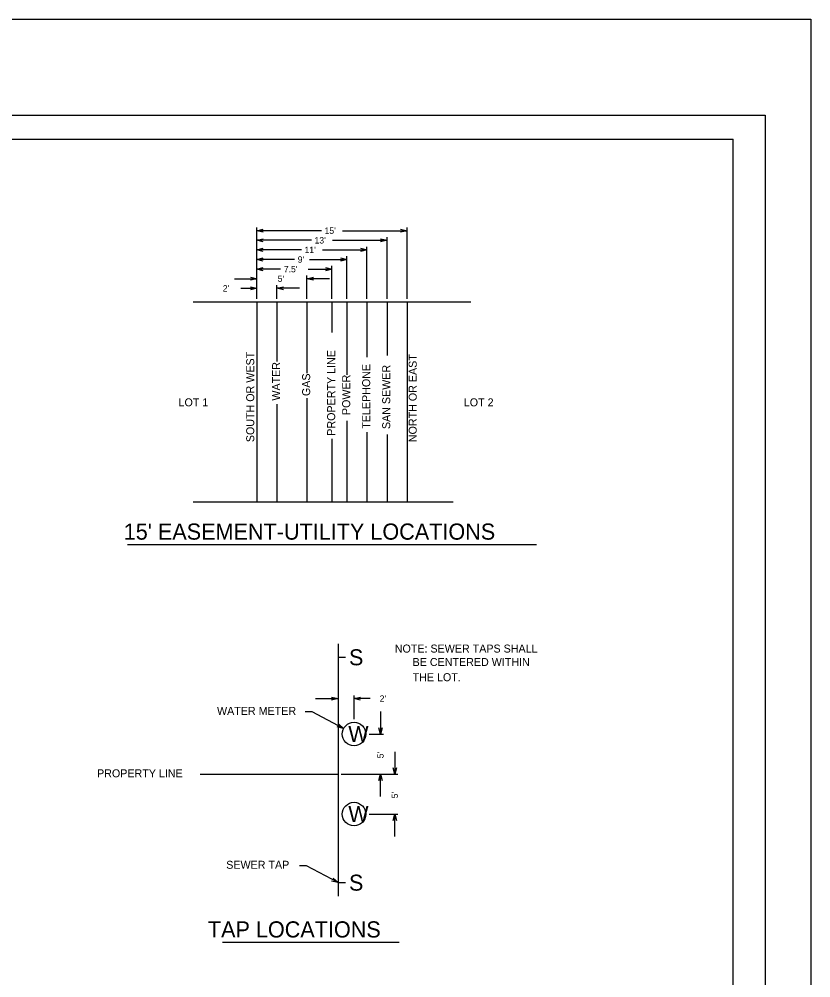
# Model space of a CAD drawing. Extents: x 524397 to 525117, y 3701341 to 3701821.
# Drawn here: x 524919 to 525116.8, y 3701581.4 to 3701821 of the extents above; entities that cross this region are included whole.
import ezdxf

# ---------------------------------------------------------------- set-up
doc = ezdxf.new("R2010")
doc.units = 0
for name, color, linetype in [('Level 1', 7, 'Continuous'), ('Level 11', 7, 'Continuous'), ('Level 9', 7, 'Continuous'), ('Pam batch print border', 7, 'Continuous')]:
    doc.layers.add(name, color=color, linetype=linetype)

msp = doc.modelspace()

# ---------------------------------------------------------------- linework, layer by layer
at = {"layer": 'Level 1'}
for p, q in [((524442.4, 3701790.98), (525097.4, 3701790.98)), ((525097.4, 3701370.98), (525097.4, 3701790.98)), ((524962.45, 3701750.32), (525031.86, 3701750.32)), ((524997.15, 3701750.32), (524997.15, 3701742.64)), ((524997.15, 3701716.03), (524997.15, 3701700.32)), ((524962.45, 3701700.32), (525027.45, 3701700.32)), ((524946.08, 3701689.72), (525048.22, 3701689.72)), ((524998.66, 3701664.86), (524998.66, 3701601.79)), ((524964.22, 3701632.3), (524998.66, 3701632.3)), ((524969.78, 3701590.3), (525013.95, 3701590.3))]:
    msp.add_line(p, q, dxfattribs=at)
at = {"layer": 'Level 11'}
for p, q in [((524978.4, 3701751.12), (524978.4, 3701768.92)), ((524978.4, 3701768.12), (524980, 3701768.52)), ((524994.5, 3701768.12), (524978.4, 3701768.12)), ((524980, 3701767.72), (524978.4, 3701768.12)), ((524999.81, 3701768.12), (525015.9, 3701768.12)), ((525014.3, 3701768.52), (525015.9, 3701768.12)), ((525015.9, 3701768.12), (525014.3, 3701767.72)), ((525015.9, 3701751.12), (525015.9, 3701768.92)), ((524978.4, 3701751.12), (524978.4, 3701766.52)), ((524978.4, 3701765.72), (524980, 3701766.12)), ((524992, 3701765.72), (524978.4, 3701765.72)), ((524980, 3701765.31), (524978.4, 3701765.72)), ((524997.31, 3701765.72), (525010.9, 3701765.72)), ((525009.3, 3701766.12), (525010.9, 3701765.72)), ((525010.9, 3701765.72), (525009.3, 3701765.31)), ((525010.9, 3701751.12), (525010.9, 3701766.52)), ((524978.4, 3701751.12), (524978.4, 3701764.11)), ((524978.4, 3701763.31), (524980, 3701763.71)), ((524989.5, 3701763.31), (524978.4, 3701763.31)), ((524980, 3701762.91), (524978.4, 3701763.31)), ((524994.81, 3701763.31), (525005.9, 3701763.31)), ((525004.3, 3701763.71), (525005.9, 3701763.31)), ((525005.9, 3701763.31), (525004.3, 3701762.91)), ((525005.9, 3701751.12), (525005.9, 3701764.11)), ((524978.4, 3701751.12), (524978.4, 3701761.71)), ((524978.4, 3701760.91), (524980, 3701761.31)), ((524987.79, 3701760.91), (524978.4, 3701760.91)), ((524980, 3701760.51), (524978.4, 3701760.91)), ((524991.51, 3701760.91), (525000.9, 3701760.91)), ((524999.3, 3701761.31), (525000.9, 3701760.91)), ((525000.9, 3701760.91), (524999.3, 3701760.51)), ((525000.9, 3701751.12), (525000.9, 3701761.71)), ((524978.4, 3701751.12), (524978.4, 3701759.31)), ((524978.4, 3701758.51), (524980, 3701758.91)), ((524984.33, 3701758.51), (524978.4, 3701758.51)), ((524980, 3701758.11), (524978.4, 3701758.51)), ((524991.22, 3701758.51), (524997.15, 3701758.51)), ((524995.55, 3701758.91), (524997.15, 3701758.51)), ((524997.15, 3701758.51), (524995.55, 3701758.11)), ((524997.15, 3701751.12), (524997.15, 3701759.31)), ((524972.8, 3701756.11), (524978.4, 3701756.11)), ((524976.8, 3701756.51), (524978.4, 3701756.11)), ((524978.4, 3701756.11), (524976.8, 3701755.71)), ((524978.4, 3701751.12), (524978.4, 3701756.91)), ((524990.9, 3701751.12), (524990.9, 3701756.91)), ((524990.9, 3701756.11), (524992.5, 3701756.51)), ((524996.51, 3701756.11), (524990.9, 3701756.11)), ((524992.5, 3701755.71), (524990.9, 3701756.11)), ((524974.4, 3701753.71), (524978.4, 3701753.71)), ((524976.8, 3701754.11), (524978.4, 3701753.71)), ((524978.4, 3701753.71), (524976.8, 3701753.31)), ((524978.4, 3701751.12), (524978.4, 3701754.51)), ((524983.4, 3701751.12), (524983.4, 3701754.51)), ((524983.4, 3701753.71), (524985, 3701754.11)), ((524989.01, 3701753.71), (524983.4, 3701753.71)), ((524985, 3701753.31), (524983.4, 3701753.71)), ((524978.4, 3701750.32), (524978.4, 3701700.32)), ((524983.4, 3701750.32), (524983.4, 3701735.42)), ((524990.9, 3701750.32), (524990.9, 3701732.53)), ((525000.9, 3701750.32), (525000.9, 3701732.07)), ((525005.9, 3701750.32), (525005.9, 3701736.52)), ((525010.9, 3701750.32), (525010.9, 3701736.93)), ((525015.9, 3701750.32), (525015.9, 3701700.32)), ((524983.4, 3701724.78), (524983.4, 3701700.32)), ((524990.9, 3701726.24), (524990.9, 3701700.32)), ((525000.9, 3701720.59), (525000.9, 3701700.32)), ((525005.9, 3701717.74), (525005.9, 3701700.32)), ((524997.15, 3701716.1), (524997.15, 3701700.32)), ((525010.9, 3701717.17), (525010.9, 3701700.32)), ((524998.66, 3701664.06), (524998.66, 3701650.36)), ((524998.66, 3701661.49), (525000.56, 3701661.49)), ((524993.06, 3701651.16), (524998.66, 3701651.16)), ((525002.66, 3701646.04), (525002.66, 3701651.97)), ((525006.66, 3701651.16), (525002.66, 3701651.16)), ((525009.25, 3701647.9), (525009.25, 3701642.3)), ((525006.41, 3701642.3), (525010.05, 3701642.3)), ((525012.84, 3701637.9), (525012.84, 3701632.3)), ((524999.46, 3701632.3), (525010.05, 3701632.3)), ((524999.46, 3701632.3), (525013.64, 3701632.3)), ((525009.25, 3701626.69), (525009.25, 3701632.3)), ((525006.41, 3701622.3), (525013.64, 3701622.3)), ((525012.84, 3701616.69), (525012.84, 3701622.3)), ((524998.66, 3701605.16), (525000.56, 3701605.16))]:
    msp.add_line(p, q, dxfattribs=at)
for points in [[(524997.06, 3701651.56), (524998.66, 3701651.16), (524997.06, 3701650.76)], [(525004.26, 3701650.76), (525002.66, 3701651.16), (525004.26, 3701651.56)], [(525000.07, 3701643.68), (524992.22, 3701647.87), (524990.42, 3701647.87)], [(524998.84, 3701644.79), (525000.07, 3701643.68), (524998.46, 3701644.08)], [(525009.65, 3701643.9), (525009.25, 3701642.3), (525008.85, 3701643.9)], [(525013.24, 3701633.9), (525012.84, 3701632.3), (525012.44, 3701633.9)], [(525008.85, 3701630.69), (525009.25, 3701632.3), (525009.65, 3701630.69)], [(525012.44, 3701620.69), (525012.84, 3701622.3), (525013.24, 3701620.69)], [(524998.66, 3701605.16), (524990.82, 3701609.36), (524989.02, 3701609.36)], [(524997.44, 3701606.27), (524998.66, 3701605.16), (524997.06, 3701605.57)]]:
    msp.add_lwpolyline(points, dxfattribs=at)
for centre in [(525002.66, 3701642.3), (525002.66, 3701622.3)]:
    msp.add_circle(centre, 2.94, dxfattribs=at)
at = {"layer": 'Level 9'}
msp.add_lwpolyline([(524396.79, 3701820.98), (525116.79, 3701820.98), (525116.79, 3701340.98), (524396.79, 3701340.98)], close=True, dxfattribs=at)
at = {"layer": 'Pam batch print border'}
msp.add_lwpolyline([(524433.4, 3701796.98), (525105.4, 3701796.98), (525105.4, 3701364.98), (524433.4, 3701364.98)], close=True, dxfattribs=at)
msp.add_lwpolyline([(524433.4, 3701796.98), (525105.4, 3701796.98), (525105.4, 3701364.98), (524433.4, 3701364.98)], close=True, dxfattribs=at)

# ---------------------------------------------------------------- texts
at = {"layer": 'Level 1'}
for s, p in [("15' EASEMENT-UTILITY LOCATIONS", (524945.13, 3701690.89)), ('TAP LOCATIONS', (524966.15, 3701591.46))]:
    msp.add_text(s, height=4.0362, dxfattribs=at).set_placement(p)
at = {"layer": 'Level 11'}
for s, height, p in [("15'", 1.601, (524995.3, 3701767.32)), ("13'", 1.601, (524992.8, 3701764.91)), ("11'", 1.601, (524990.3, 3701762.51)), ("9'", 1.601, (524988.59, 3701760.11)), ("7.5'", 1.601, (524985.13, 3701757.71)), ("5'", 1.601, (524983.59, 3701755.31)), ("2'", 1.601, (524969.88, 3701752.91)), ('LOT 1', 2, (524958.82, 3701724.21)), ('LOT 2', 2, (525030.09, 3701724.21)), ('NOTE: SEWER TAPS SHALL', 2, (525012.84, 3701662.67)), ('S', 4, (525001.42, 3701659.49)), ('      BE CENTERED WITHIN', 2, (525012.84, 3701659.31)), ('      THE LOT.', 2, (525012.84, 3701655.51)), ("2'", 1.601, (525009.07, 3701650.36)), ('WATER METER', 2, (524968.43, 3701647.1)), ('W', 4, (525001.24, 3701640.3)), ('PROPERTY LINE', 2, (524938.46, 3701631.49)), ('W', 4, (525001.24, 3701620.3)), ('SEWER TAP', 2, (524970.73, 3701608.63)), ('S', 4, (525001.42, 3701603.16))]:
    msp.add_text(s, height=height, dxfattribs=at).set_placement(p)
for s, height, p in [('SOUTH OR WEST', 2, (524977.73, 3701715.26)), ('PROPERTY LINE', 2, (524997.95, 3701716.87)), ('NORTH OR EAST', 2, (525018.32, 3701715.26)), ('WATER', 2, (524984.2, 3701725.64)), ('TELEPHONE', 2, (525006.7, 3701718.62)), ('SAN SEWER', 2, (525011.7, 3701718.53)), ('GAS', 2, (524991.7, 3701726.78)), ('POWER', 2, (525001.7, 3701722.03)), ("5'", 1.601, (525010.05, 3701636.24)), ("5'", 1.601, (525013.64, 3701626.24))]:
    msp.add_text(s, height=height, rotation=90, dxfattribs=at).set_placement(p)

doc.saveas('drawing.dxf')
